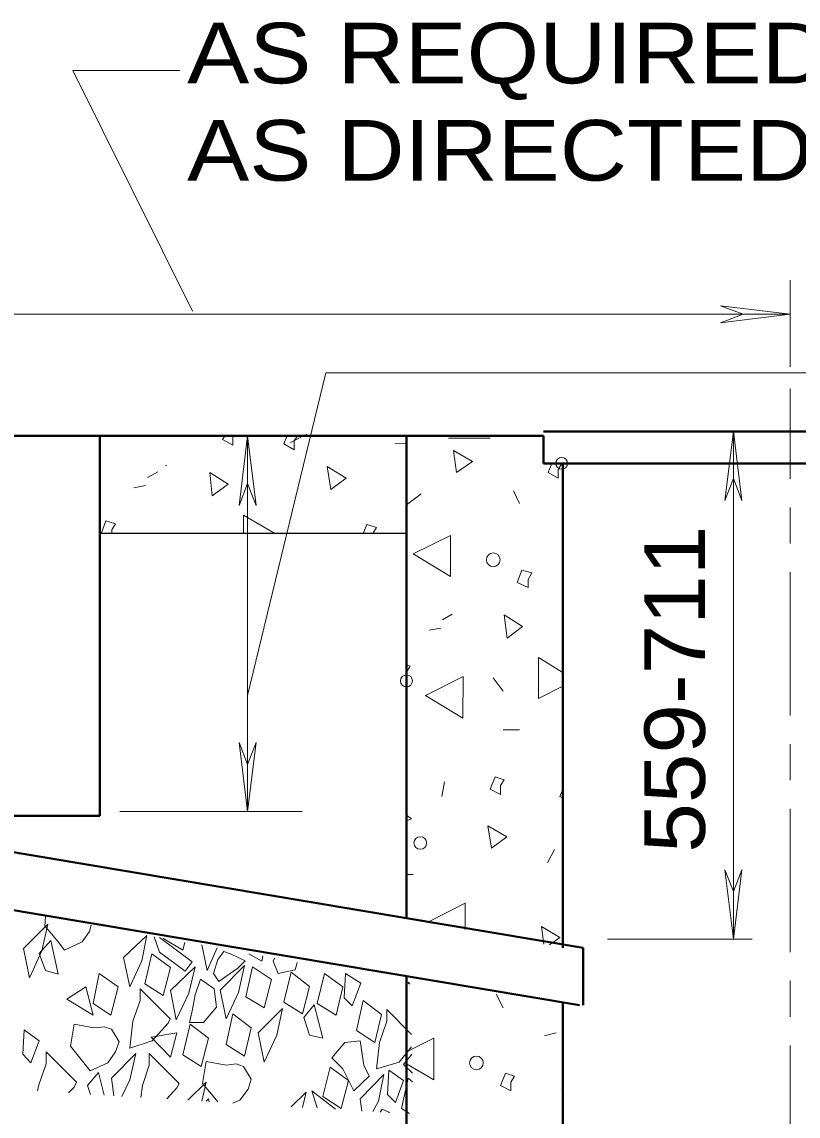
# Model space of a CAD drawing. Extents: x 312583 to 312854, y 144419 to 144597.
# Drawn here: x 312703.46 to 312713.21, y 144438.88 to 144452.61 of the extents above; entities that cross this region are included whole.
import ezdxf

# ---------------------------------------------------------------- set-up
doc = ezdxf.new("R2010")
doc.units = 0
doc.header["$LTSCALE"] = 0.3
doc.header["$PDMODE"] = 32
doc.header["$PDSIZE"] = 0.15
doc.linetypes.add('LONG_DASH_SHORT_DASH', pattern=[9.9, 6, -1.2, 1.5, -1.2])
doc.layers.add('1', color=7, linetype='Continuous', lineweight=40)
doc.layers.add('2', color=7, linetype='Continuous', lineweight=13)

msp = doc.modelspace()

# ---------------------------------------------------------------- linework, layer by layer
at = {"layer": '1', "lineweight": 25}
msp.add_line((312705.2782, 144447.0454), (312705.2705, 144447.0377), dxfattribs=at)
at = {"layer": '2'}
for p, q in [((312704.1052, 144451.9981), (312705.4468, 144451.9981)), ((312704.1052, 144451.9981), (312705.6078, 144448.9774)), ((312713.1058, 144448.2797), (312713.1058, 144449.3684)), ((312712.2318, 144449.0464), (312712.5155, 144448.9391)), ((312713.1058, 144448.9391), (312712.2318, 144449.0464)), ((312702.0275, 144448.9391), (312713.1058, 144448.9391)), ((312712.2318, 144448.8317), (312712.5155, 144448.9391)), ((312713.1058, 144448.9391), (312712.2318, 144448.8317)), ((312707.2792, 144448.2031), (312706.2978, 144444.1551)), ((312707.2792, 144448.2031), (312715.9655, 144448.2031)), ((312712.3928, 144447.4671), (312712.2855, 144446.6007)), ((312712.3928, 144447.4671), (312712.5002, 144446.6007)), ((312706.1138, 144447.4057), (312706.1215, 144447.4057)), ((312706.2978, 144447.4134), (312706.1905, 144446.5394)), ((312706.2978, 144447.4134), (312706.2978, 144442.6984)), ((312706.2978, 144447.4134), (312706.4052, 144446.5394)), ((312706.8345, 144447.3291), (312707.0415, 144447.4364)), ((312706.8805, 144447.3521), (312706.9188, 144447.4057)), ((312709.3415, 144447.3827), (312708.8202, 144447.3827)), ((312710.1925, 144446.9917), (312710.2385, 144447.0684)), ((312705.0405, 144446.8921), (312705.1708, 144446.9611)), ((312704.8718, 144446.7617), (312705.0175, 144446.7924)), ((312706.1905, 144446.5394), (312706.2978, 144446.8154)), ((312706.4052, 144446.5394), (312706.2978, 144446.8154)), ((312712.2855, 144446.6007), (312712.3928, 144446.8767)), ((312712.5002, 144446.6007), (312712.3928, 144446.8767)), ((312709.6328, 144446.7234), (312709.7095, 144446.5624)), ((312706.2442, 144446.4167), (312706.2442, 144446.1944)), ((312706.6275, 144446.1944), (312706.2442, 144446.4167)), ((312704.5958, 144446.1867), (312704.5958, 144446.2327)), ((312710.2385, 144446.1944), (312710.2538, 144446.1944)), ((312708.7435, 144445.1057), (312708.8662, 144445.1747)), ((312708.5748, 144444.9754), (312708.7205, 144444.9984)), ((312710.2462, 144444.4464), (312709.9472, 144444.6304)), ((312708.2912, 144444.3391), (312708.2912, 144444.4464)), ((312709.3798, 144444.3774), (312709.5025, 144444.2087)), ((312709.5025, 144443.7257), (312709.7095, 144443.7257)), ((312706.1905, 144443.5647), (312706.2978, 144443.2887)), ((312706.2978, 144442.6984), (312706.1905, 144443.5647)), ((312706.4052, 144443.5647), (312706.2978, 144443.2887)), ((312706.2978, 144442.6984), (312706.4052, 144443.5647)), ((312708.7358, 144442.8901), (312708.7665, 144443.0741)), ((312704.6955, 144442.6984), (312706.9802, 144442.6984)), ((312710.1465, 144442.2231), (312710.0622, 144442.0544)), ((312712.2855, 144441.9701), (312712.3928, 144441.6941)), ((312712.3928, 144441.0961), (312712.2855, 144441.9701)), ((312712.5002, 144441.9701), (312712.3928, 144441.6941)), ((312712.3928, 144441.0961), (312712.5002, 144441.9701)), ((312708.2912, 144441.9087), (312708.3755, 144441.9087)), ((312705.1248, 144441.1267), (312705.1938, 144440.9351)), ((312705.2475, 144441.1037), (312705.2398, 144441.1114)), ((312710.8135, 144441.0961), (312712.6305, 144441.0961)), ((312709.4182, 144440.4061), (312709.5025, 144440.2374)), ((312710.0238, 144439.8847), (312710.1695, 144439.9231)), ((312708.2912, 144439.5321), (312708.6362, 144439.3327)), ((312704.6188, 144439.1334), (312704.5882, 144439.3557)), ((312704.2892, 144439.2637), (312704.3275, 144439.1487)), ((312705.9068, 144439.0797), (312705.9222, 144439.0567)), ((312707.7315, 144438.9417), (312707.7085, 144439.0951)), ((312708.3295, 144438.9111), (312708.2298, 144438.9724)), ((312708.0765, 144438.9187), (312708.0688, 144438.9264))]:
    msp.add_line(p, q, dxfattribs=at)
at = {"layer": '2', "linetype": 'LONG_DASH_SHORT_DASH'}
msp.add_line((312713.1058, 144434.9934), (312713.1058, 144448.0037), dxfattribs=at)
at = {"layer": '2', "lineweight": 40}
for p, q in [((312704.4425, 144447.4134), (312703.1928, 144447.4134)), ((312704.4425, 144442.6447), (312704.4425, 144447.4134)), ((312708.2912, 144447.4134), (312704.4425, 144447.4134)), ((312708.2912, 144447.4134), (312710.0085, 144447.4134)), ((312710.0085, 144447.0684), (312710.0085, 144447.4134)), ((312702.0352, 144442.6447), (312704.4425, 144442.6447)), ((312702.0198, 144442.4147), (312710.5068, 144440.9887)), ((312701.9202, 144441.7017), (312710.4608, 144440.2681)), ((312710.5068, 144440.9887), (312710.5068, 144440.2681)), ((312708.2912, 144434.9934), (312708.2912, 144440.6361)), ((312710.2538, 144434.9934), (312710.2538, 144440.3064))]:
    msp.add_line(p, q, dxfattribs=at)
at = {"layer": '2', "lineweight": 25}
msp.add_line((312708.2912, 144446.1867), (312704.4425, 144446.1867), dxfattribs=at)
at = {"layer": '2', "lineweight": 35}
msp.add_line((312708.3065, 144440.5594), (312708.3295, 144440.5364), dxfattribs=at)
at = {"layer": '2', "lineweight": 40}
for points in [[(312710.0085, 144447.4671), (312712.9755, 144447.4671), (312716.2415, 144447.4671)], [(312710.0085, 144447.0684), (312712.9755, 144447.0684), (312716.2415, 144447.0684), (312716.2415, 144447.4671)], [(312708.2912, 144441.3567), (312708.2912, 144442.8441), (312708.2912, 144447.4134)], [(312710.2538, 144440.9887), (312710.2538, 144442.8441), (312710.2538, 144447.0684)]]:
    msp.add_lwpolyline(points, dxfattribs=at)
at = {"layer": '2'}
for points in [[(312712.3928, 144447.4671), (312712.3928, 144442.8441), (312712.3928, 144441.0961)], [(312706.0065, 144447.4057), (312705.9835, 144447.3674), (312706.1138, 144447.2984), (312706.1138, 144447.4057)], [(312706.7885, 144447.4057), (312706.7502, 144447.3137), (312706.8805, 144447.2371), (312706.8805, 144447.3521)], [(312708.1455, 144447.3137), (312708.2835, 144447.3214), (312708.2912, 144447.3214)], [(312710.1158, 144447.0684), (312710.0698, 144446.9534), (312710.1925, 144446.8844), (312710.1925, 144446.9917)], [(312708.4752, 144446.6851), (312708.2912, 144446.5471), (312708.2912, 144446.5547)], [(312704.5958, 144446.2327), (312704.6418, 144446.3094), (312704.5192, 144446.3477), (312704.4655, 144446.1944), (312704.4808, 144446.1867)], [(312707.8695, 144446.1867), (312707.9155, 144446.2634), (312707.7928, 144446.3017), (312707.7468, 144446.1867)], [(312709.9472, 144444.6304), (312709.9472, 144444.1167), (312710.2462, 144444.2701)], [(312708.2912, 144444.4464), (312708.3372, 144444.5231), (312708.2988, 144444.5384)], [(312710.2538, 144442.9821), (312710.2155, 144442.8901), (312710.2538, 144442.8671)], [(312708.2912, 144442.5834), (312708.3525, 144442.6064), (312708.2912, 144442.6524)], [(312709.0272, 144441.2187), (312709.0272, 144441.5484), (312708.5595, 144441.3107), (312708.5825, 144441.3031)], [(312703.7602, 144441.3797), (312703.7525, 144441.2647), (312703.9212, 144441.0654)], [(312703.9212, 144441.0654), (312703.9978, 144440.9581), (312704.2202, 144441.0654), (312704.3122, 144441.1957), (312704.3352, 144441.2724)], [(312710.0852, 144441.0271), (312710.2155, 144441.1191), (312709.9855, 144441.2571), (312710.0162, 144441.0347)], [(312705.1938, 144440.9351), (312705.5158, 144440.6974), (312705.6002, 144440.8124), (312705.1938, 144441.1191)], [(312705.5082, 144441.0577), (312705.4852, 144440.9581), (312705.2475, 144441.1037)], [(312705.9145, 144440.9887), (312705.7918, 144440.7051), (312705.7228, 144441.0271)], [(312706.4895, 144440.8891), (312706.4742, 144440.8201), (312706.3132, 144440.9121)], [(312706.6352, 144440.8584), (312706.6198, 144440.8201), (312706.6812, 144440.6667), (312706.8958, 144440.7127), (312706.9188, 144440.8047)], [(312708.3525, 144439.9001), (312708.0458, 144440.2144), (312708.0458, 144440.0687)], [(312708.0458, 144440.0687), (312707.9538, 144439.8004), (312707.9155, 144439.4707), (312708.1992, 144439.5551), (312708.3525, 144439.7467)], [(312708.6362, 144439.3327), (312708.6362, 144439.8541), (312708.2912, 144439.6854)], [(312704.0515, 144439.1717), (312704.1205, 144439.2407), (312704.1512, 144439.3021), (312703.7678, 144439.6854), (312703.7678, 144439.5321)], [(312704.5882, 144439.3557), (312704.8948, 144439.6624), (312704.8182, 144439.3327), (312704.7185, 144439.1257)], [(312705.2858, 144439.0951), (312705.4085, 144439.2331), (312705.4392, 144439.2867), (312705.0635, 144439.6624), (312705.0635, 144439.5167)], [(312708.3602, 144439.6547), (312708.2528, 144439.5244), (312708.3678, 144439.4171)], [(312703.7678, 144439.5321), (312703.6758, 144439.2714), (312703.6605, 144439.1947)], [(312705.0635, 144439.5167), (312704.9792, 144439.2637), (312704.9562, 144439.1104)], [(312706.1138, 144439.0414), (312706.1982, 144439.0797), (312706.3055, 144439.2177), (312706.3438, 144439.3404), (312706.2442, 144439.5014), (312706.1522, 144439.5321), (312706.0295, 144439.5167), (312705.7765, 144439.5627), (312705.7305, 144439.2867), (312705.9068, 144439.0797)], [(312704.4962, 144439.1411), (312704.4272, 144439.4247), (312704.2892, 144439.2637)], [(312707.7085, 144439.0951), (312708.0075, 144439.4017), (312707.9385, 144439.0644), (312707.8695, 144438.9341)], [(312708.2298, 144438.9724), (312708.3142, 144439.3557), (312708.3678, 144439.3097)], [(312705.5465, 144439.0797), (312705.7765, 144439.3021), (312705.7228, 144439.0644)], [(312710.2538, 144439.2407), (312710.2385, 144439.2177), (312710.2538, 144439.1947)], [(312705.8148, 144439.0567), (312705.8072, 144439.0951), (312705.7765, 144439.0644)], [(312706.8422, 144438.9954), (312707.0338, 144439.1794), (312706.9878, 144438.9877)], [(312707.4018, 144438.9647), (312707.1028, 144439.1947), (312707.1718, 144438.9801)], [(312708.0688, 144438.9264), (312707.9845, 144438.9647), (312707.9615, 144438.9264)]]:
    msp.add_lwpolyline(points, dxfattribs=at)
for points in [[(312708.9198, 144446.9534), (312709.1192, 144447.0914), (312708.8815, 144447.2294)], [(312705.8532, 144446.6621), (312706.0525, 144446.8077), (312705.8225, 144446.9534)], [(312707.3405, 144446.7387), (312707.5322, 144446.8844), (312707.2945, 144447.0301)], [(312708.8432, 144445.6501), (312708.8432, 144446.1637), (312708.3755, 144445.9337)], [(312709.8168, 144445.6117), (312709.8628, 144445.6961), (312709.7402, 144445.7267), (312709.6788, 144445.5734), (312709.8168, 144445.5121)], [(312709.5562, 144444.8757), (312709.7478, 144445.0214), (312709.5178, 144445.1671)], [(312708.9965, 144443.8714), (312709.0042, 144444.3927), (312708.5288, 144444.1551)], [(312709.4718, 144443.0281), (312709.5178, 144443.0971), (312709.4028, 144443.1354), (312709.3415, 144442.9821), (312709.4718, 144442.9131)], [(312709.3568, 144442.2384), (312709.5485, 144442.3841), (312709.3108, 144442.5221)], [(312703.4842, 144440.9811), (312703.7908, 144441.2877), (312703.7142, 144440.9504), (312703.5608, 144440.6131)], [(312704.7415, 144440.8661), (312705.0328, 144441.1421), (312704.9715, 144440.8277), (312704.8182, 144440.4981)], [(312703.6835, 144440.9197), (312703.7602, 144440.7051), (312703.9212, 144440.6591), (312703.8292, 144441.0807)], [(312705.0098, 144440.5364), (312705.0942, 144440.9121), (312705.3318, 144440.7434), (312705.2398, 144440.3907)], [(312706.0832, 144440.9121), (312705.9988, 144440.9427), (312705.9222, 144440.8431), (312705.8685, 144440.6667), (312705.9375, 144440.5671), (312706.0372, 144440.6361), (312706.1752, 144440.7357), (312706.2672, 144440.8277)], [(312705.3318, 144440.4521), (312705.6385, 144440.7511), (312705.5618, 144440.4214), (312705.4008, 144440.0841)], [(312705.9528, 144440.4597), (312706.2595, 144440.7664), (312706.1828, 144440.4291), (312706.0295, 144440.0994)], [(312706.2748, 144440.3754), (312706.3592, 144440.7511), (312706.5968, 144440.5901), (312706.5048, 144440.2374)], [(312704.3582, 144440.2911), (312704.4348, 144440.6667), (312704.6725, 144440.4981), (312704.5805, 144440.1454)], [(312705.7075, 144440.5977), (312705.6385, 144440.3984), (312705.6002, 144440.1991), (312705.5695, 144440.0534), (312705.7458, 144440.0534), (312705.9068, 144440.2451), (312705.8762, 144440.4751)], [(312706.7502, 144440.3064), (312706.8422, 144440.6821), (312707.0722, 144440.5057), (312706.9878, 144440.1607)], [(312707.1718, 144440.2911), (312707.2638, 144440.6667), (312707.4938, 144440.4981), (312707.4095, 144440.1454)], [(312707.5245, 144440.6667), (312707.5092, 144440.3601), (312707.6088, 144440.2604), (312707.7162, 144440.5441)], [(312704.0285, 144440.3447), (312704.3582, 144440.1454), (312704.2662, 144440.4981)], [(312704.9485, 144440.3294), (312704.8565, 144440.0687), (312704.8182, 144439.7314), (312705.1018, 144439.8234), (312705.3012, 144440.0457), (312705.3242, 144440.0994), (312704.9485, 144440.4751)], [(312707.6625, 144439.9537), (312707.7468, 144440.3294), (312707.9768, 144440.1531), (312707.8925, 144439.8004)], [(312706.4282, 144439.9231), (312706.7348, 144440.2297), (312706.6658, 144439.8924), (312706.5048, 144439.5551)], [(312707.0032, 144440.1147), (312707.0722, 144439.8924), (312707.2408, 144439.8541), (312707.1335, 144440.2757)], [(312704.2432, 144439.5474), (312704.3198, 144439.4477), (312704.5422, 144439.5474), (312704.6418, 144439.6854), (312704.6878, 144439.8081), (312704.5882, 144439.9691), (312704.4962, 144439.9997), (312704.3658, 144439.9844), (312704.1205, 144440.0304), (312704.0745, 144439.7544)], [(312705.4852, 144439.6471), (312705.5772, 144440.0304), (312705.8072, 144439.8541), (312705.7152, 144439.5014)], [(312706.0295, 144439.7774), (312706.1138, 144440.1607), (312706.3438, 144439.9844), (312706.2595, 144439.6317)], [(312703.4918, 144439.9614), (312703.4765, 144439.6547), (312703.5762, 144439.5474), (312703.6835, 144439.8234)], [(312705.0865, 144439.8694), (312705.3318, 144439.6164), (312705.4085, 144439.9231)], [(312707.6318, 144439.1947), (312707.4938, 144439.4707), (312707.3558, 144439.6087), (312707.5168, 144439.8004), (312707.7085, 144439.8234), (312707.7545, 144439.5167), (312707.8235, 144439.3787)], [(312707.2408, 144439.1257), (312707.3328, 144439.4937), (312707.5628, 144439.3251), (312707.4708, 144438.9724)], [(312708.0688, 144439.4554), (312708.0535, 144439.1487), (312708.1532, 144439.0491), (312708.2528, 144439.3251)], [(312709.6022, 144439.3021), (312709.6482, 144439.3787), (312709.5332, 144439.4171), (312709.4718, 144439.2637), (312709.6022, 144439.1947)]]:
    msp.add_lwpolyline(points, close=True, dxfattribs=at)
for centre, radius in [((312709.3805, 144445.8586), 0.0867), ((312708.4639, 144442.3049), 0.0785), ((312709.1685, 144439.545), 0.0867)]:
    msp.add_circle(centre, radius, dxfattribs=at)
for p in [(312710.2385, 144447.0684), (312708.2912, 144444.3391)]:
    msp.add_point(p, dxfattribs=at)

# ---------------------------------------------------------------- texts
at = {"layer": '2', "width": 1.15}
for s, p in [('AS REQUIRED BY PLANS OR ', (312705.5388, 144451.8361)), ('AS DIRECTED BY THE ENGINEER', (312705.5388, 144450.6161))]:
    msp.add_text(s, height=0.76, dxfattribs=at).set_placement(p)
at = {"layer": '2', "width": 1.1}
msp.add_text('559-711', height=0.76, rotation=90, dxfattribs=at).set_placement((312712.0364, 144442.1833))

doc.saveas('drawing.dxf')
